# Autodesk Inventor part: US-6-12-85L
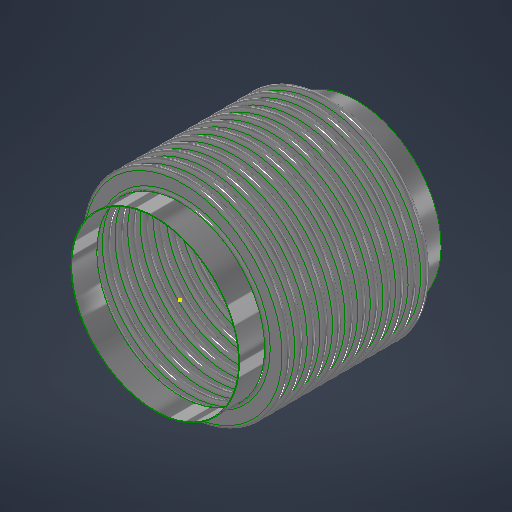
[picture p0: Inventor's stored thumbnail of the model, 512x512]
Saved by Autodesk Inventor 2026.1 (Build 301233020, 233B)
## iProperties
Category: 22 GA (0.030 THICK)
RuleStatus: InUse
Created: 2026-07
Part Number: US-6-12-85L
Project: =STOCK BELLOWS: <Stock Number><SFILL>
Material: ASTM A240-304
Description: =STOCK BELLOWS: <Stock Number>, <SID_> I.D., <SOD_> O.D., <SPLY_> PLY, <Category>, <SNET_CONS> CONS.<PITCH_><STANGENT_> TANGENT<SFILL>
Document SubType Name: Sheet Metal
Designer: LC
Stock Number: U.S-6-12-85L
Surface Area: 659.127 cm^2
Volume: 56.61 cm^3
Sheet Metal Rule: Default
Appearance: STAINLESS STEEL
NET_TUBE: 3.428
COUNTER: 1.500
PBAR: 1.214
PSET: 5.356
PLY: 2
CONS: 2
THK: 0.036
ID: 4.500
OD: 5.500
CONS_: 2
TANGENT: 0.500
PITCH: 0.375
BELLOWS_UPSET: 0.000
NET_CONS: 2
S_CONS: 0
Description_Units: 0
ID_M: 114.30 mm
OD_M: 139.70 mm
THK_M: 0.91 mm
ID_U: 4.500 in
OD_U: 5.500 in
THK_U: 0.036 in
TANGENT2: 0.500
d79: 1.000
d82: 1.000
d83: 26.000
d84: 24.000
d80: 2.571
d81: 10
SID: 2.375
SCONS_: 12
SPITCH: 0.250
SBELLOWS_UPSET: 0.000
SNET_CONS: 12
SS_CONS: 0
SCONS: 8
d174: 8
d177: 0.018
d178: 2.375
d179: 3.000
d180: 0.375
d181: 1.000
d182: 0.000
d190: 8
d191: 1
d192: 1
d193: 8
d194: 0
PART_NUMBER: U.S-6-12-85L
PRESSURE: 85
SIZE: 6.00
STANGENT_: 1.000
d214: 8
d217: 0.030
d218: 6.625
d219: 8.125
d220: 0.500
d221: 1.000
d222: 0.000
d230: 8
d231: 1
d232: 1
d233: 8
d234: 0
STANGENT: 4.000
SPLY_: 1
STHK_: 0.030
SID_: 6.625
SOD_: 8.125
SPITCH_: 0.500
STANGENT__: 1.000
SBELLOWS_UPSET_: 0.000
SDIFF_TAN: 1.000
TAN_TO_TAN: 0.750 in
d252: 2
d275: 2
d287: 0.050
d289: 0.500
d290: 0.000
d263: 2
d265: 1
d268: 2
d269: 0
d286: 2
d288: 1
d291: 2
d292: 0
SOD_NECK: 6 11/16
CFILL: .
SFILL: .
PITCH_: =, <SPITCH_> PITCH,
SREROLL: 0.750
MATTABLE: 20 GA (0.036 THICK)
MESH: ,
CSECT: 2
Author: LC
Keywords: 20 GA (0.036 THICK)
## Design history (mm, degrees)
sketch "Sketch2"
  geometry: L1 (0, -183.595)-(0, 600.956) reference; L2 (58.979, 0)-(57.15, 0); L3 (60.446, -1.467)-(66.554, -1.467); L4 (60.446, -3.296)-(66.554, -3.296); L5 (66.554, -8.058)-(60.446, -8.058); L6 (66.554, -6.229)-(60.446, -6.229); L7 (58.979, -9.525)-(57.15, -9.525); L8 (60.446, 0)-(60.446, -9.525); L9 (66.554, -4.762)-(69.85, -4.763); L10 (57.15, 0)-(57.15, -9.525); L11 (20.376, 102.841)-(20.376, 101.926); L12 (58.262, 488.877)-(58.262, 349.177); L13 (58.262, 479.352)-(58.262, 339.652); L14 (93.133, -58.817)-(93.133, -71.517); L15 (118.746, -66.401)-(118.746, -66.401); L16 (66.554, -6.229)-(66.554, -8.058); L17 (60.446, -6.229)-(60.446, -8.058); L18 (60.446, -7.144)-(66.554, -7.144); L19 (69.85, 0)-(69.85, -9.525); L20 (-66.554, -6.229)-(-66.554, -8.058); L21 (-66.554, -1.467)-(-60.446, -1.467); L22 (-66.554, -3.296)-(-60.446, -3.296); L23 (-60.446, -6.229)-(-66.554, -6.229); L24 (-66.554, -7.144)-(-60.446, -7.144); L25 (-60.446, -8.058)-(-66.554, -8.058); L26 (-60.446, -6.229)-(-60.446, -8.058); L27 (-57.15, -2.522)-(-57.15, -12.047); L28 (-60.446, -4.763)-(-57.15, -4.763); L29 (-66.554, 3.828)-(-66.554, -9.525); L30 (-68.021, 0)-(-69.85, 0); L31 (-69.85, 0)-(-69.85, -9.525); L32 (-68.021, -9.525)-(-69.85, -9.525); A1 r 1.467 centre (60.446, 0) between (58.979, 0) and (60.446, -1.467); A2 r 3.296 centre (60.446, 0) between (57.15, 0) and (60.446, -3.296); A3 r 3.296 centre (66.554, -4.762) between (66.554, -8.058) and (66.554, -1.467); A4 r 1.467 centre (66.554, -4.762) between (66.554, -6.229) and (66.554, -3.296); A5 r 1.467 centre (60.446, -9.525) between (60.446, -8.058) and (58.979, -9.525); A6 r 3.296 centre (60.446, -9.525) between (60.446, -6.229) and (57.15, -9.525); A7 r 2.381 centre (66.554, -4.762) between (66.554, -7.144) and (68.936, -4.762); A8 r 2.381 centre (60.446, -9.525) between (60.446, -7.144) and (58.064, -9.525); A9 r 1.467 centre (-66.554, -9.525) between (-66.554, -8.058) and (-68.021, -9.525); A10 r 1.467 centre (-60.446, -4.763) between (-60.446, -6.229) and (-60.446, -3.296); A11 r 2.381 centre (-60.446, -4.763) between (-60.446, -7.144) and (-58.064, -4.763); A12 r 3.296 centre (-60.446, -4.763) between (-60.446, -8.058) and (-60.446, -1.467); A13 r 2.381 centre (-66.554, -9.525) between (-66.554, -7.144) and (-68.936, -9.525); A14 r 3.296 centre (-66.554, -9.525) between (-66.554, -6.229) and (-69.85, -9.525); A15 r 1.467 centre (-66.554, 0) between (-68.021, 0) and (-66.554, -1.467); A16 r 3.296 centre (-66.554, 0) between (-69.85, 0) and (-66.554, -3.296); 10 further points
  constraints: 62 end point, 38 point on circle, 20 tangent, 16 centre point, 12 parallel, 9 midpoint, 7 vertical, 6 coincident, 6 concentric, 6 point on line, 4 equal radius, 4 perpendicular, 3 horizontal, 1 collinear, 1 horizontal alignment, 10 other
  dimensions: "THK" = 0.9144 distance of L11.start L11.end; "ID" = 114.3 distance of L11.end point (20.376, -12.374); "OD" = 139.7 distance of L12.start L12.end; "PITCH" = 9.525 distance of L12.start L13.start; "TANGENT" = 12.7 distance of L14.start L14.end; "BELLOWS_UPSET" = 0 distance of L15.start L15.end; "d43" = 114.3 diameter of L10 L1 (= ID); "d44" = 139.7 diameter of L9.end L1 (= OD); "d45" = 1.8288 distance between parallel lines of L5 L6 (computed from THK, PLY); "d46" = 3.29565 radius of A3 (computed from PITCH, THK, PLY); "UPSET_PITCH" = 9.525 distance of L2.end L7.end (derived); "SIDEWALL_ANGLE" = 0 deg angle of L3 L9 (derived); "CON_GAP" = 2.9337 distance of point (60.446, -6.229) point (60.446, -3.296) (derived); "TAN1" = 3.74046 dimension on A8 (derived); "TAN2" = 3.74046 dimension on A7 (derived); "LEG1" = 6.1087 distance of L18.start L18.end (derived); "d278" = 1.8288 distance between parallel lines of L25 L23 (derived); "d279" = 3.29565 radius of A12 (derived); "d280" = 9.525 distance of L30.end L31.end (derived); "d281" = 360 deg dimension on L21 L28 (derived); "d282" = 2.9337 distance of point (-66.554, -6.229) point (-66.554, -3.296) (derived); "d283" = 3.74046 dimension on A13 (derived); "d284" = 3.74046 dimension on A11 (derived); "d285" = 6.1087 distance of L24.start L24.end (derived); "d293" = 114.3 diameter of L27 L1 (derived); "d294" = 139.7 diameter of L31 L1 (derived)
  node "Sketch Rectangular Pattern1" dims "d31" = 25.4, "ID" = 114.3
  node "Sketch Rectangular Pattern2" dims "d39" = 25.4, "PITCH" = 9.525
revolve "CONS" stored, may be unused: angle "d48" = 90 deg
node "BELLOW MIDPLANE"
pattern_linear "Rectangular Pattern2" dims "d52" = 9.525 (= UPSET_PITCH)
sketch "Sketch5"
  geometry: C1 r 58.979 at (0, 0) reference; C2 r 57.15 at (0, 0) reference
extrude "TANGENT" new body sketch "Sketch5" distance "d53" = 12.7 (= TANGENT); taper "d54" = 0 deg
revolve "SAMETAN" stored, may be unused: angle "d65" = 90 deg
revolve "DIFFTAN" stored, may be unused: angle "d70" = 90 deg
sketch "Sketch9"
  geometry: L1 (58.391, 0)-(-58.391, 0) reference; L2 (0, -17.78)-(0, 17.78) reference; L3 (41.708, 0)-(-41.708, 0); L4 (41.708, -11.906)-(41.708, 11.906); L5 (29.008, -11.906)-(29.008, 11.906); L6 (15.418, 11.906)-(15.418, -11.906); L7 (-29.008, -11.906)-(-29.008, 11.906); L8 (-41.708, -11.906)-(-41.708, 11.906); L9 (40.914, -11.906)-(40.914, 11.906); L10 (41.708, -11.906)-(40.914, -11.906); L11 (41.708, 11.906)-(40.914, 11.906); L12 (15.815, 11.906)-(15.022, 11.906); L13 (15.022, 11.906)-(15.022, -11.906); L14 (15.022, -11.906)-(15.815, -11.906); L15 (15.815, -11.906)-(15.815, 11.906); L16 (-15.815, 11.906)-(-15.815, -11.906); L17 (-15.418, 11.906)-(-15.418, -11.906); L18 (-15.815, -11.906)-(-15.022, -11.906); L19 (-15.022, -11.906)-(-15.022, 11.906); L20 (-15.022, 11.906)-(-15.815, 11.906); L21 (-41.708, -11.906)-(-40.914, -11.906); L22 (-40.914, -11.906)-(-40.914, 11.906); L23 (-40.914, 11.906)-(-41.708, 11.906); L24 (-41.708, 11.906)-(-41.708, -11.906); L25 (41.708, -0.397)-(-41.708, -0.397); L26 (-41.708, -0.397)-(-41.708, 0.397); L27 (-41.708, 0.397)-(41.708, 0.397); L28 (41.708, 0.397)-(41.708, -0.397); L29 (-41.708, 11.906)-(41.708, 11.906); L30 (41.708, 11.906)-(41.708, 12.7); L31 (41.708, 12.7)-(-41.708, 12.7); L32 (-41.708, 12.7)-(-41.708, 11.906); L33 (41.708, -11.906)-(-41.708, -11.906); L34 (-41.708, -11.906)-(-41.708, -12.7); L35 (-41.708, -12.7)-(41.708, -12.7); L36 (41.708, -12.7)-(41.708, -11.906); 30 further points
  constraints: 68 end point, 13 midpoint, 13 parallel, 8 horizontal, 7 perpendicular, 6 equal length, 3 point on line, 2 vertical, 14 other
  dimensions: "d115" = 23.8125 distance of L4.start L4.end (derived); "d116" = 12.7 distance between parallel lines of L4 L5 (derived); "d117" = 13.58962 distance between parallel lines of L5 L6 (derived); "d125" = 44.42645 distance between parallel lines of L7 L6 (derived); "d127" = 12.7 distance between parallel lines of L8 L7 (derived); "d128" = 26.28962 distance between parallel lines of L6 L4 (derived); "d130" = 83.41607 distance between parallel lines of L8 L4 (derived); "RULER_THK" = 0.79375 distance between parallel lines of L4 L9; "d135" = 0.79375 distance of L13.end L14.end (derived); "d138" = 30.83684 distance of L13.end L16.end (derived); "d143" = 0.79375 distance of L22.end L8.end (derived); "d144" = 0.79375 distance between parallel lines of L27 L25 (derived)
extrude "RULER" join sketch "Sketch9" distance "d149" = 0.79375 (derived); taper "d150" = 0 deg
extrude "BARS" join sketch "Sketch9" distance "d151" = 0.79375 (derived); taper "d152" = 0 deg
pattern_linear "Rectangular Pattern4" dims "d155" = 30.83684 (derived)
sketch "Sketch13"
  geometry: L1 (93.149, -52.467)-(93.149, -77.867); L2 (84.9, 0)-(84.138, 0); L3 (84.9, -12.7)-(84.138, -12.7); L4 (99.631, -9.906)-(87.694, -9.906); L5 (99.632, -9.144)-(87.694, -9.144); L6 (99.631, -6.35)-(103.188, -6.35); L7 (87.694, -2.794)-(99.631, -2.794); L8 (87.694, 0)-(87.694, -12.7); L9 (84.138, 0)-(84.138, -12.7); L10 (58.254, -329.214)-(58.254, -535.589); L11 (58.254, -341.914)-(58.254, -548.289); L12 (58.254, -367.314)-(58.254, -573.689); L13 (58.254, -380.014)-(58.254, -586.389); L14 (58.254, -392.714)-(58.254, -599.089); L15 (58.254, -405.414)-(58.254, -611.789); L16 (58.254, -418.114)-(58.254, -624.489); L17 (58.254, -354.614)-(58.254, -560.989); L18 (20.376, 102.688)-(20.376, 101.926); L19 (87.694, -3.556)-(99.631, -3.556); L20 (0, -717.834)-(0, 239.264) reference; L21 (-23.752, 0)-(142.514, 0) reference; A1 r 2.794 centre (87.694, 0) between (84.9, 0) and (87.694, -2.794); A2 r 2.794 centre (87.694, -12.7) between (87.694, -9.906) and (84.9, -12.7); A3 r 3.556 centre (87.694, -12.7) between (87.694, -9.144) and (84.138, -12.7); A4 r 2.794 centre (99.631, -6.35) between (99.632, -9.144) and (99.631, -3.556); A5 r 3.556 centre (99.631, -6.35) between (99.631, -9.906) and (99.631, -2.794); A6 r 3.556 centre (87.694, 0) between (84.138, 0) and (87.694, -3.556); 6 further points; 1 other entity
  constraints: 38 end point, 15 point on circle, 9 tangent, 6 centre point, 6 parallel, 5 vertical alignment, 4 point on line, 4 vertical, 3 coincident, 3 concentric, 2 collinear, 2 equal radius, 1 horizontal, 1 perpendicular, 23 other
  dimensions: "SBELLOWS_UPSET_" = 0 distance of point (118.762, -66.401) point (118.762, -66.401); "STOTAL_THK_BELLOW__" = 0.762 distance between parallel lines of L4 L5 (derived); "d224" = 3.556 radius of A5 (derived); "d225" = 12.7 distance of L2.end L3.end (derived); "SSIDEWALL_ANGLE_" = 0 deg angle of L7 L6 (derived); "SSCON_GAP_" = 5.588 distance of point (87.694, -9.144) point (87.694, -3.556) (derived); "d235" = 168.275 diameter of L9 L20 (derived); "d236" = 206.375 diameter of L6.end L20 (derived)
  node "Sketch Rectangular Pattern4" dims "d228" = 25.4
  node "Sketch Rectangular Pattern5" dims "d229" = 25.4
revolve "SBELLOW" stored, may be unused: angle "d197" = 90 deg
pattern_linear "Rectangular Pattern5" dims "d204" = 12.7 (derived)
revolve "STANGENT" stored, may be unused: angle "d240" = 90 deg
revolve "SSAMETAN" stored, may be unused: angle "d241" = 90 deg
revolve "SDIFFTAN" stored, may be unused: angle "d246" = 90 deg
revolve "INVCON" stored, may be unused: angle "d295" = 90 deg
pattern_linear "Rectangular Pattern6" dims "d298" = 9.525 (derived)
revolve "INVTANGENT" stored, may be unused: angle "d302" = 90 deg
revolve "INVSAMETAN" stored, may be unused: angle "d307" = 90 deg
revolve "INVDIFFTAN" stored, may be unused: angle "d312" = 90 deg
sketch "ID BELLOW MOUNT CALC"
  geometry: L1 (44.45, 0)-(38.1, 0); L2 (38.1, 0)-(38.1, 12.7); L3 (38.1, 12.7)-(44.45, 12.7); L4 (44.45, 12.7)-(44.45, 0); L5 (36.513, 12.7)-(34.684, 12.7); L6 (34.684, 12.7)-(34.684, 0); L7 (34.684, 0)-(36.513, 0); L8 (36.513, 0)-(36.513, 12.7); L9 (0, -2.54)-(0, 15.24) reference; L10 (-8.89, 0)-(53.34, 0) reference; 1 further point
  constraints: 16 end point, 5 parallel, 2 collinear, 2 horizontal, 2 perpendicular
  dimensions: "d314" = 12.7 distance of L5.end L6.end (derived); "d315" = 1.8288 distance of L5.start L5.end (derived); "IG" = 1.5875 distance between parallel lines of L2 L8; "PIPE_OD" = 88.9 diameter of L4 L9; "PIPE_WALL" = 6.35 distance of L2.end L3.end; "ID_MT_BELLOW" = 69.3674 diameter of L6 L9 (derived)
revolve "CFILL" stored, may be unused: angle "d320" = 90 deg
pattern_linear "Rectangular Pattern7" dims "d323" = 9.525 (derived)
revolve "SFILL" stored, may be unused: angle "d324" = 90 deg
pattern_linear "Rectangular Pattern8" dims "d327" = 12.7 (derived)
node "STOCK BELLOW MIDPLANE"
sketch "Sketch21"
  geometry: L1 (0, -144.462)-(0, 144.462) reference; L2 (-144.462, 0)-(144.462, 0) reference; L3 (-0.099, 71.437)-(0.099, 71.437); L4 (0.099, 71.437)-(0.099, 55.562); L5 (0.099, 55.562)-(-0.099, 55.562); L6 (-0.099, 55.562)-(-0.099, 71.437); C1 r 55.562 at (0, 0); C2 r 71.437 at (0, 0); 3 further points
  constraints: 8 end point, 2 centre point, 2 coincident, 2 parallel, 2 tangent, 1 horizontal, 1 perpendicular, 1 other
  dimensions: "d329" = 111.125 diameter of C1 (derived); "d330" = 142.875 diameter of C2 (derived); "d331" = 0.19844 distance of L3.start L3.end
extrude "CLAMSHELL" cut sketch "Sketch21" extent not by distance; stored distance "d332" = 0; taper "d333" = 0 deg
pattern_circular "Circular Pattern1" dims angle "d335" = 180 deg (derived)
node "BELLOW"
sketch "Sketch6"
  geometry: L1 (-19.05, 58.979)-(-6.35, 58.979); L2 (-6.35, 58.979)-(-6.35, 57.15); L3 (-6.35, 57.15)-(-19.05, 57.15); L4 (-19.05, 57.15)-(-19.05, 58.979); L5 (2.54, 0)-(-59.69, 0) reference; L6 (-38.1, -108.388)-(-38.1, 156.601) reference; 1 further point
  constraints: 8 end point, 2 parallel, 1 horizontal, 1 perpendicular
  dimensions: "d61" = 12.7 distance of L2.end L3.end (derived); "d62" = 1.8288 distance of L1.end L2.end (derived); "d63" = 114.3 diameter of L3 L5 (derived); "d64" = 19.05 distance between parallel lines of L4 L6 (derived)
sketch "Sketch12"
  geometry: 1 further point
sketch "Sketch14"
  geometry: L1 (-25.4, 84.9)-(0, 84.9); L2 (0, 84.9)-(0, 84.138); L3 (0, 84.138)-(-25.4, 84.138); L4 (-25.4, 84.138)-(-25.4, 84.9); L5 (5.08, 0)-(-30.48, 0) reference; L6 (0, -14.252)-(0, 85.512) reference; 1 further point
  constraints: 8 end point, 2 parallel, 1 collinear, 1 horizontal, 1 perpendicular
  dimensions: "d237" = 0.762 distance of L3.end L1.start (derived); "d238" = 168.275 diameter of L3 L5 (derived); "d239" = 25.4 distance of L1.start L1.end (derived); "SOD_NECK" = 169.799 diameter of L1 L5 (derived)
sketch "Sketch15"
  geometry: L1 (-14.252, 0)-(85.512, 0) reference; L2 (84.138, -152.4)-(84.9, -152.4); L3 (84.9, -152.4)-(84.9, -177.8); L4 (84.9, -177.8)-(84.138, -177.8); L5 (84.138, -177.8)-(84.138, -152.4); L6 (0, -170.18)-(0, 43.18) reference; 1 further point
  constraints: 8 end point, 2 parallel, 1 horizontal, 1 perpendicular
  dimensions: "d205" = 25.4 distance of L4.end L2.start (derived); "d206" = 0.762 distance of L3.end L4.end (derived); "d207" = 168.275 diameter of L5 L6 (derived); "d208" = 152.4 distance between parallel lines of L1 L2 (derived)
node "TANGENT_"
node "SAME_TAN"
sketch "Sketch8"
  geometry: L1 (58.979, -19.05)-(57.15, -19.05); L2 (57.15, -19.05)-(57.15, -31.75); L3 (57.15, -31.75)-(58.979, -31.75); L4 (58.979, -31.75)-(58.979, -19.05); L5 (0, -40.64)-(0, 21.59) reference; L6 (-108.388, 0)-(156.601, 0) reference; 1 further point
  constraints: 8 end point, 2 parallel, 1 horizontal, 1 perpendicular
  dimensions: "d66" = 114.3 diameter of L2 L5 (derived); "TOTAL_THK_BELLOW" = 1.8288 distance of L2.end L3.end (derived); "d68" = 19.05 distance between parallel lines of L1 L6 (derived); "d69" = 12.7 distance of L1.end L2.end (derived)
node "DIFF_TAN"
node "Sketch Rectangular Pattern3" dims "d138" = 30.83684 (derived), "d141" = 25.4
node "SBELLOW_"
node "STANGENT_"
node "SSAME_TAN"
sketch "Sketch16"
  geometry: L1 (84.9, -152.4)-(84.138, -152.4); L2 (84.138, -152.4)-(84.138, -177.8); L3 (84.138, -177.8)-(84.9, -177.8); L4 (84.9, -177.8)-(84.9, -152.4); L5 (0, -170.18)-(0, 43.18) reference; L6 (-14.252, 0)-(85.512, 0) reference; 1 further point
  constraints: 8 end point, 2 parallel, 1 horizontal, 1 perpendicular
  dimensions: "SDIFF_TAN" = 25.4 distance of L3.end L1.start; "d243" = 0.762 distance of L2.end L3.end (derived); "d244" = 152.4 distance between parallel lines of L1 L6 (derived); "d245" = 168.275 diameter of L2 L5 (derived)
node "SDIFF_TAN"
body "Solid15"
sketch "Sketch17"
  geometry: L1 (69.85, 12.7)-(68.021, 12.7); L2 (68.021, 12.7)-(68.021, 0); L3 (68.021, 0)-(69.85, 0); L4 (69.85, 0)-(69.85, 12.7); L5 (0, -2.54)-(0, 15.24) reference; L6 (-13.97, 0)-(83.82, 0) reference; 2 further points
  constraints: 8 end point, 2 parallel, 1 horizontal, 1 midpoint, 1 perpendicular, 1 point on line
  dimensions: "INVTANGENT" = 12.7 distance of L3.end L1.start (derived); "d300" = 1.8288 distance of L1.start L1.end (derived); "d301" = 139.7 diameter of L4 L5 (derived)
body "Solid16"
sketch "Sketch18"
  geometry: L1 (69.85, -19.05)-(68.021, -19.05); L2 (68.021, -19.05)-(68.021, -31.75); L3 (68.021, -31.75)-(69.85, -31.75); L4 (69.85, -31.75)-(69.85, -19.05); L5 (-13.97, 0)-(83.82, 0) reference; L6 (0, -40.64)-(0, 21.59) reference; 1 further point
  constraints: 8 end point, 2 parallel, 1 horizontal, 1 perpendicular
  dimensions: "d303" = 19.05 distance between parallel lines of L1 L5 (derived); "d304" = 12.7 distance of L3.end L1.start (derived); "d305" = 1.8288 distance of L2.end L3.end (derived); "d306" = 139.7 diameter of L4 L6 (derived)
body "Solid17"
sketch "Sketch19"
  geometry: L1 (69.85, -19.05)-(68.021, -19.05); L2 (68.021, -19.05)-(68.021, -31.75); L3 (68.021, -31.75)-(69.85, -31.75); L4 (69.85, -31.75)-(69.85, -19.05); L5 (0, -40.64)-(0, 21.59) reference; L6 (-13.97, 0)-(83.82, 0) reference; 1 further point
  constraints: 8 end point, 2 parallel, 1 horizontal, 1 perpendicular
  dimensions: "d308" = 12.7 distance of L1.end L2.end (derived); "d309" = 139.7 diameter of L4 L5 (derived); "d310" = 1.8288 distance of L2.end L3.end (derived); "d311" = 19.05 distance between parallel lines of L1 L6 (derived)
body "Solid18"
body "Solid19"
body "Solid20"
other parameters: "BMPL" = -76.2, "PSET" = 136.0424 (computed from OD, THK, PLY) [user parameter], "PBAR" = 30.83684 (= 0.570796 x PITCH + OD - ID) [user parameter; used in 1 equation term], "COUNTER" = 15 [user parameter], "NET_TUBE" = 87.07367 (computed from CONS_, PBAR, TANGENT) [user parameter], "S_CONS" = 0 [user parameter; used in 1 equation term], "ID_M" = 114.3 (= ID) [user parameter], "OD_M" = 139.7 (= OD) [user parameter], "THK_M" = 0.9144 (= THK) [user parameter], "ID_U" = 114.3 (= ID) [user parameter], "OD_U" = 139.7 (= OD) [user parameter], "THK_U" = 0.9144 (= THK) [user parameter], "D_UNITS" = 0 [user parameter], "TANGENT2" = 12.7 [user parameter], "TAN_TO_TAN" = 19.05 [user parameter], "OD_NECK" = 117.9576 [user parameter], "d79" = 25.4, "d80" = 65.29823 [user parameter], "d82" = 25.4, "d83" = 660.4, "d84" = 609.6, "sa_0" = 4, "FRAME_THK" = 0.79375 [user parameter], "CON_FLAT" = 13.58962 [user parameter], "SID" = 60.325 [user parameter], "SPITCH" = 6.35 [user parameter], "STANGENT_" = 25.4 [user parameter], "SBELLOWS_UPSET" = 0 [user parameter], "SS_CONS" = 0 [user parameter], "STAN_TO_TAN_" = 152.4 [user parameter], "d100" = 0.762 [user parameter], "d191" = 25.4 [user parameter], "d194" = 0 [user parameter], "STANGENT" = 101.6 [user parameter], "d234" = 0 [user parameter], "SUPSET_PITCH_" = 12.7 [user parameter], "d269" = 0 [user parameter], "d287" = 1.27, "d289" = 12.7, "d290" = 0, "d292" = 0 [user parameter], "Thickness" = 3.048 (derived), "KFactor" = 4.4, "BendRadius" = 3.048 (derived), "BendReliefWidth" = 3.048 (derived), "BendReliefDepth" = 1.524 (derived), "CornerReliefSize" = 12.192 (derived), "SeamGap" = 0.00508, "MinimumRemnant" = 6.096 (derived), "TransitionRadius" = 3.048 (derived), "JacobiRadiusSize" = 3.048 (derived), "GapSize" = 3.048 (derived), "SREROLL" = 19.05 [user parameter], "CUR_STK_PITCH" = 12.7 [user parameter], "d328" = -76.2 (derived), "CSECTDEG" = 180 deg [user parameter]
